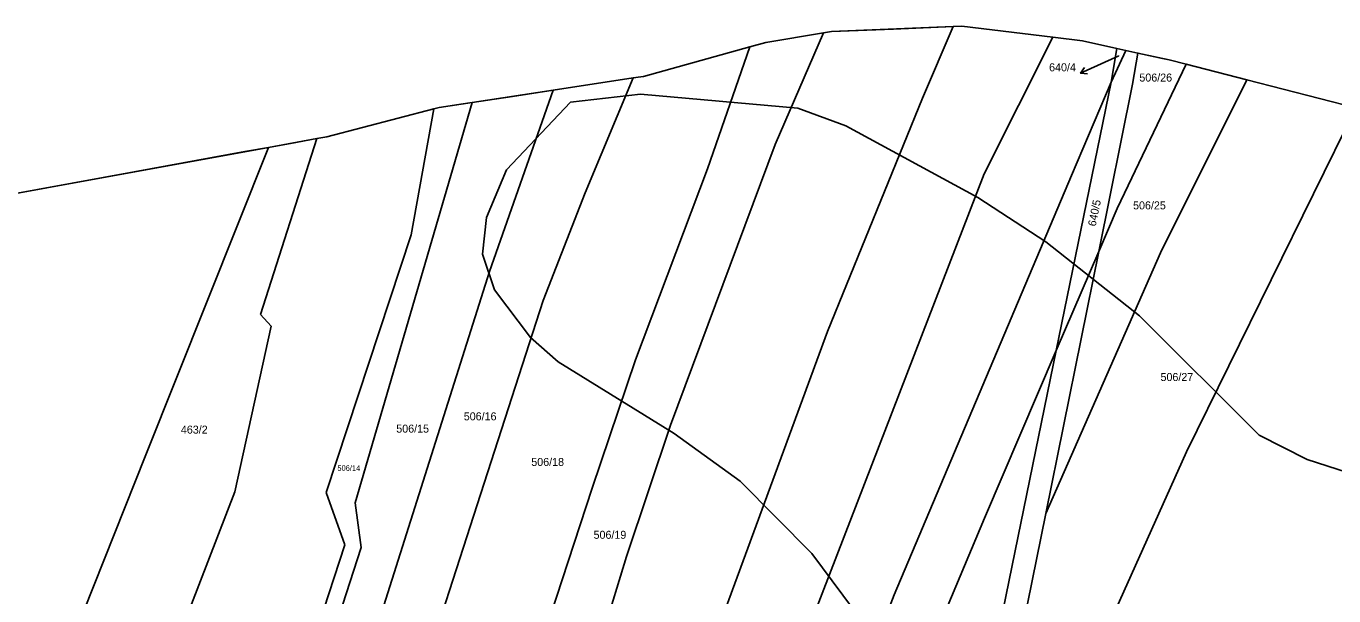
# Model space of a CAD drawing. Extents: x -743888 to -742027, y -1128394 to -1126768.
# Drawn here: x -742758.2 to -742480.3, y -1126888.9 to -1126767.8 of the extents above; entities that cross this region are included whole.
import ezdxf

# ---------------------------------------------------------------- set-up
doc = ezdxf.new("R2010")
doc.units = 0
for name, color, linetype in [('Vrstva 1', 7, 'Continuous'), ('Vrstva 13', 7, 'Continuous'), ('Vrstva 16', 7, 'Continuous'), ('Vrstva 18', 7, 'Continuous'), ('Vrstva 52', 7, 'Continuous'), ('Vrstva 6', 7, 'Continuous')]:
    doc.layers.add(name, color=color, linetype=linetype)

msp = doc.modelspace()

# ---------------------------------------------------------------- linework, layer by layer
at = {"layer": 'Vrstva 1'}
for points in [[(-742527.67, -1126779.74), (-742526.41, -1126772.54)], [(-742523.09, -1126780.11), (-742521.95, -1126773.52)], [(-742539.32, -1126836.74), (-742527.67, -1126779.74)], [(-742530.29, -1126815.68), (-742523.09, -1126780.11)], [(-742541.56, -1126871.36), (-742530.29, -1126815.68)], [(-742550.57, -1126891.8), (-742539.32, -1126836.74)], [(-742553.22, -1126928.98), (-742541.56, -1126871.36)]]:
    msp.add_lwpolyline(points, dxfattribs=at)
at = {"layer": 'Vrstva 13'}
for points in [[(-742601.05, -1126771.3), (-742588.76, -1126769.25)], [(-742588.76, -1126769.25), (-742587.09, -1126768.97)], [(-742587.09, -1126768.97), (-742573.9, -1126768.42)], [(-742573.9, -1126768.42), (-742561.23, -1126767.89)], [(-742561.23, -1126767.89), (-742559.37, -1126767.81)], [(-742559.37, -1126767.81), (-742540.06, -1126770.15)], [(-742540.06, -1126770.15), (-742533.77, -1126770.91)], [(-742627.03, -1126778.48), (-742604.44, -1126772.24)], [(-742604.44, -1126772.24), (-742601.05, -1126771.3)], [(-742533.77, -1126770.91), (-742526.41, -1126772.54)], [(-742526.41, -1126772.54), (-742524.54, -1126772.95)], [(-742524.54, -1126772.95), (-742521.95, -1126773.52)], [(-742521.95, -1126773.52), (-742516.73, -1126774.67)], [(-742516.73, -1126774.67), (-742515.35, -1126774.98)], [(-742515.35, -1126774.98), (-742511.74, -1126775.91)], [(-742627.56, -1126778.56), (-742627.03, -1126778.48)], [(-742511.74, -1126775.91), (-742498.85, -1126779.22)], [(-742646.21, -1126781.41), (-742629.18, -1126778.81)], [(-742629.18, -1126778.81), (-742627.56, -1126778.56)], [(-742665.8, -1126784.4), (-742663.45, -1126784.04)], [(-742663.45, -1126784.04), (-742654.84, -1126782.73)], [(-742654.84, -1126782.73), (-742646.21, -1126781.41)], [(-742694.29, -1126791.31), (-742671.59, -1126785.41)], [(-742671.59, -1126785.41), (-742670.45, -1126785.11)], [(-742670.45, -1126785.11), (-742665.8, -1126784.4)], [(-742700.87, -1126792.51), (-742696.43, -1126791.7)], [(-742696.43, -1126791.7), (-742694.29, -1126791.31)], [(-742735.24, -1126798.77), (-742711.7, -1126794.48)], [(-742711.7, -1126794.48), (-742706.72, -1126793.58)], [(-742706.72, -1126793.58), (-742700.87, -1126792.51)], [(-742769.01, -1126804.93), (-742735.24, -1126798.77)]]:
    msp.add_lwpolyline(points, dxfattribs=at)
at = {"layer": 'Vrstva 16'}
msp.add_line((-742532.66, -1126777.96), (-742534.16, -1126777.82), dxfattribs=at)
for points in [[(-742526.01, -1126774.1), (-742530.52, -1126776.16)], [(-742530.52, -1126776.16), (-742534.16, -1126777.82), (-742533.29, -1126776.6)]]:
    msp.add_lwpolyline(points, dxfattribs=at)
at = {"layer": 'Vrstva 52'}
for points in [[(-742800.98, -1126810.76), (-742706.72, -1126793.58), (-742696.43, -1126791.7), (-742694.29, -1126791.31), (-742671.59, -1126785.41), (-742670.45, -1126785.11), (-742663.45, -1126784.04), (-742646.21, -1126781.41), (-742629.18, -1126778.81), (-742627.03, -1126778.48), (-742604.44, -1126772.24), (-742601.05, -1126771.3), (-742588.76, -1126769.25), (-742587.09, -1126768.97), (-742561.23, -1126767.89), (-742559.37, -1126767.81), (-742540.06, -1126770.15), (-742533.77, -1126770.91), (-742526.41, -1126772.54), (-742524.54, -1126772.95), (-742521.95, -1126773.52), (-742515.35, -1126774.98), (-742511.74, -1126775.91), (-742498.85, -1126779.22), (-742475.66, -1126785.18)], [(-742578.06, -1126897.63), (-742591.25, -1126879.88), (-742606.5, -1126864.5), (-742620.5, -1126854.38), (-742645.13, -1126839.13), (-742651.06, -1126834), (-742658.69, -1126823.88), (-742661.25, -1126816.25), (-742660.38, -1126808.5), (-742656.13, -1126798.38), (-742642.56, -1126784), (-742627.69, -1126782.25), (-742594.19, -1126785.25), (-742584, -1126789), (-742556, -1126804.25), (-742541.56, -1126813.63), (-742521.63, -1126829.38), (-742496.19, -1126854.75), (-742486, -1126859.88), (-742469.06, -1126865.38)]]:
    msp.add_lwpolyline(points, dxfattribs=at)
at = {"layer": 'Vrstva 6'}
for points in [[(-742599.04, -1126792.93), (-742588.76, -1126769.25)], [(-742567.77, -1126783.13), (-742561.23, -1126767.89)], [(-742554.63, -1126799.18), (-742540.06, -1126770.15)], [(-742613.44, -1126798.13), (-742604.44, -1126772.24)], [(-742527.67, -1126779.74), (-742524.54, -1126772.95)], [(-742526.39, -1126806.59), (-742511.74, -1126775.91)], [(-742639.39, -1126803.22), (-742629.18, -1126778.81)], [(-742536.1, -1126799.53), (-742527.67, -1126779.74)], [(-742517.16, -1126816.01), (-742498.85, -1126779.22)], [(-742688.27, -1126869.14), (-742663.45, -1126784.04)], [(-742659.71, -1126819.94), (-742646.21, -1126781.41)], [(-742587.89, -1126832.72), (-742567.77, -1126783.13)], [(-742676.36, -1126812.17), (-742671.59, -1126785.41)], [(-742511.64, -1126858.28), (-742475.66, -1126785.18)], [(-742708.37, -1126829.06), (-742696.43, -1126791.7)], [(-742732.76, -1126858.93), (-742706.72, -1126793.58)], [(-742621.29, -1126852.62), (-742599.04, -1126792.93)], [(-742628.71, -1126838.73), (-742613.44, -1126798.13)], [(-742603.91, -1126926.94), (-742554.63, -1126799.18)], [(-742573.73, -1126888.65), (-742536.1, -1126799.53)], [(-742648.33, -1126826.13), (-742639.39, -1126803.22)], [(-742530.29, -1126815.68), (-742526.39, -1126806.59)], [(-742694.48, -1126866.91), (-742676.36, -1126812.17)], [(-742541.56, -1126871.36), (-742517.16, -1126816.01)], [(-742539.32, -1126836.74), (-742530.29, -1126815.68)], [(-742691.49, -1126920.27), (-742659.71, -1126819.94)], [(-742688.91, -1126951.77), (-742648.33, -1126826.13)], [(-742708.37, -1126829.06), (-742706.14, -1126831.54)], [(-742713.83, -1126866.81), (-742706.14, -1126831.54)], [(-742634.42, -1126959.12), (-742587.89, -1126832.72)], [(-742554.59, -1126872.35), (-742539.32, -1126836.74)], [(-742637.92, -1126865.97), (-742628.71, -1126838.73)], [(-742630.66, -1126880.5), (-742621.29, -1126852.62)], [(-742750.49, -1126903.46), (-742732.76, -1126858.93)], [(-742562.72, -1126972.14), (-742511.64, -1126858.28)], [(-742730.7, -1126910.48), (-742713.83, -1126866.81)], [(-742694.48, -1126866.91), (-742690.51, -1126878.08)], [(-742650.59, -1126904.79), (-742637.92, -1126865.97)], [(-742688.27, -1126869.14), (-742687.03, -1126878.58)], [(-742577.05, -1126926.06), (-742554.59, -1126872.35)], [(-742719.6, -1126967.23), (-742690.51, -1126878.08)], [(-742712.23, -1126956.56), (-742687.03, -1126878.58)], [(-742645.29, -1126928.59), (-742630.66, -1126880.5)], [(-742601.46, -1126960.43), (-742573.73, -1126888.65)]]:
    msp.add_lwpolyline(points, dxfattribs=at)

# ---------------------------------------------------------------- texts
at = {"layer": 'Vrstva 16'}
msp.add_text('640/4', height=1.7, dxfattribs=at).set_placement((-742540.83, -1126777.41))
at = {"layer": 'Vrstva 18'}
for s, height, p in [('640/4', 0.1, (-742526.01, -1126774.1)), ('506/26', 1.7, (-742521.65, -1126779.59)), ('506/25', 1.7, (-742522.99, -1126806.75)), ('506/27', 1.7, (-742517.16, -1126843.23)), ('506/16', 1.7, (-742665.21, -1126851.59)), ('463/2', 1.7, (-742725.32, -1126854.41)), ('506/15', 1.7, (-742679.55, -1126854.2)), ('506/14', 1.19, (-742692.07, -1126862.33)), ('506/18', 1.7, (-742650.86, -1126861.28)), ('506/19', 1.7, (-742637.63, -1126876.76))]:
    msp.add_text(s, height=height, dxfattribs=at).set_placement(p)
msp.add_text('640/5', height=1.7, rotation=78.484, dxfattribs=at).set_placement((-742530.94, -1126810.46))

doc.saveas('drawing.dxf')
